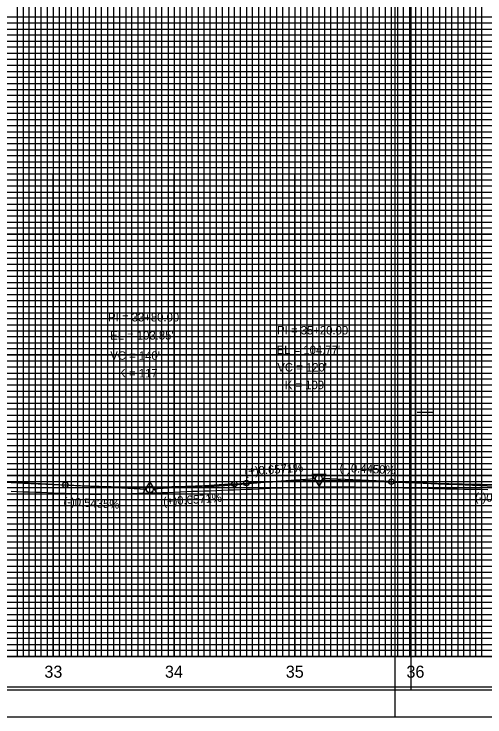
# Model space of a CAD drawing. Extents: x 2345490 to 2436403, y 465165 to 573888.
# Drawn here: x 2384034 to 2384424, y 515088 to 515670 of the extents above; entities that cross this region are included whole.
import ezdxf

# ---------------------------------------------------------------- set-up
doc = ezdxf.new("R2010")
doc.units = 0
for name, color, linetype in [('Old_Level_1', 7, 'Continuous'), ('Old_Level_18', 7, 'Continuous'), ('Old_Level_2', 7, 'Continuous'), ('Old_Level_41', 7, 'Continuous'), ('Old_Level_42', 7, 'Continuous'), ('Old_Level_43', 7, 'Continuous'), ('Old_Level_50', 7, 'Continuous'), ('Old_Level_51', 7, 'Continuous'), ('Old_Level_52', 7, 'Continuous'), ('Old_Level_57', 7, 'Continuous'), ('Old_Level_61', 7, 'Continuous'), ('Old_Level_62', 7, 'Continuous'), ('Old_Level_63', 7, 'Continuous')]:
    doc.layers.add(name, color=color, linetype=linetype)

msp = doc.modelspace()

# ---------------------------------------------------------------- linework, layer by layer
at = {"layer": 'Old_Level_1'}
for points in [[(2384031.799, 515274.675), (2384036.799, 515274.44575), (2384041.799, 515274.20725), (2384046.799, 515274.04575), (2384051.799, 515273.88425), (2384056.799, 515273.7225), (2384061.799, 515273.561), (2384066.799, 515273.325), (2384071.799, 515273.08175), (2384076.799, 515272.8975), (2384081.799, 515272.733), (2384086.799, 515272.5685), (2384091.799, 515272.404), (2384096.799, 515272.2395), (2384101.799, 515272.07525), (2384106.799, 515272.1845), (2384111.799, 515272.4225), (2384116.799, 515272.634), (2384121.799, 515272.47), (2384126.799, 515272.38825), (2384131.799, 515272.6185), (2384136.799, 515272.849), (2384141.799, 515273.0795), (2384146.799, 515273.2615), (2384151.799, 515273.335), (2384156.799, 515273.43025), (2384161.799, 515273.65775), (2384166.799, 515273.885), (2384171.799, 515274.11225), (2384176.799, 515274.34875), (2384181.799, 515274.6045), (2384186.799, 515274.76825), (2384191.799, 515274.84125), (2384196.799, 515274.91375), (2384201.799, 515275.149), (2384206.799, 515275.39775), (2384211.799, 515275.6445), (2384216.799, 515275.87125), (2384221.799, 515276.03275), (2384226.799, 515276.19275), (2384231.799, 515276.42275), (2384236.799, 515276.66), (2384241.799, 515276.8955), (2384246.799, 515277.1075), (2384251.799, 515277.259), (2384256.799, 515277.409), (2384261.799, 515277.5455), (2384266.799, 515277.6785)], [(2384266.799, 515277.6785), (2384271.799, 515277.81), (2384276.799, 515277.9495), (2384281.799, 515278.08025), (2384286.799, 515278.2065), (2384291.799, 515278.331), (2384296.799, 515278.3855), (2384301.799, 515278.29375), (2384306.799, 515278.2), (2384311.799, 515278.1535), (2384316.799, 515278.11775), (2384321.799, 515278.08), (2384326.799, 515278.02075), (2384331.799, 515277.91725), (2384336.799, 515277.81175), (2384341.799, 515277.75325), (2384346.799, 515277.7055), (2384351.799, 515277.60875), (2384356.799, 515277.495), (2384361.799, 515277.4345), (2384366.799, 515277.3775), (2384371.799, 515277.26125), (2384376.799, 515277.04725), (2384381.799, 515276.83125), (2384386.799, 515276.7395), (2384391.799, 515276.672), (2384396.799, 515276.60225), (2384401.799, 515276.47275), (2384406.799, 515276.3895), (2384411.799, 515276.3405), (2384416.799, 515276.28225), (2384421.799, 515276.2015), (2384426.799, 515276.11875)]]:
    msp.add_lwpolyline(points, dxfattribs=at)
at = {"layer": 'Old_Level_18'}
msp.add_lwpolyline([(2384616.79875, 516162.5265), (2383116.79875, 516162.5265), (2383116.79875, 515112.5265), (2384616.79875, 515112.5265)], close=True, dxfattribs=at)
at = {"layer": 'Old_Level_2'}
for p, q in [((2383991.799, 515284.4505), (2384076.799, 515279.831)), ((2384076.799, 515279.831), (2384144.05325, 515276.17575)), ((2384216.799, 515280.62675), (2384149.54325, 515276.207)), ((2384216.799, 515280.62675), (2384226.799, 515281.28375)), ((2384226.799, 515281.28375), (2384284.055, 515285.0465)), ((2384346.799, 515282.55675), (2384289.5465, 515285.1045)), ((2384346.799, 515282.55675), (2384484.05175, 515276.449))]:
    msp.add_line(p, q, dxfattribs=at)
for points in [[(2384292.72475, 515288.51125), (2384280.98225, 515288.49675), (2384286.86575, 515278.3785)], [(2384140.99325, 515272.5755), (2384152.73575, 515272.5755), (2384146.86475, 515282.70125)]]:
    msp.add_lwpolyline(points, close=True, dxfattribs=at)
for centre, radius in [((2384286.799, 515285.22675), 2.75), ((2384286.799, 515285.22675), 2.75), ((2384076.799, 515279.831), 2.25), ((2384216.799, 515280.62675), 2.25), ((2384226.799, 515281.28375), 2.25), ((2384346.799, 515282.55675), 2.25), ((2384146.799, 515276.0265), 2.75), ((2384146.799, 515276.0265), 2.75)]:
    msp.add_circle(centre, radius, dxfattribs=at)
for points in [[(2384076.799, 515279.831), (2384079.599, 515279.68225), (2384082.399, 515279.54), (2384085.199, 515279.40475), (2384087.999, 515279.276), (2384090.799, 515279.15425), (2384093.599, 515279.039), (2384096.399, 515278.9305), (2384099.199, 515278.82875), (2384101.999, 515278.73375), (2384104.799, 515278.6455), (2384107.599, 515278.56375), (2384110.399, 515278.489), (2384113.199, 515278.42075), (2384115.999, 515278.3595), (2384118.799, 515278.30475), (2384121.599, 515278.25675), (2384124.399, 515278.2155), (2384127.199, 515278.181), (2384129.999, 515278.15325), (2384132.799, 515278.13225), (2384135.599, 515278.11775), (2384138.399, 515278.11025), (2384141.199, 515278.10925), (2384143.999, 515278.11525), (2384146.799, 515278.12775), (2384149.599, 515278.147), (2384152.399, 515278.173), (2384155.199, 515278.20575), (2384157.999, 515278.24525), (2384160.799, 515278.29125), (2384163.599, 515278.34425), (2384166.399, 515278.40375), (2384169.199, 515278.47025), (2384171.999, 515278.54325), (2384174.799, 515278.623), (2384177.599, 515278.7095), (2384180.399, 515278.80275), (2384183.199, 515278.90275), (2384185.999, 515279.0095), (2384188.799, 515279.12275), (2384191.599, 515279.243), (2384194.399, 515279.36975), (2384197.199, 515279.50325), (2384199.999, 515279.64375), (2384202.799, 515279.79075), (2384205.599, 515279.9445), (2384208.399, 515280.105), (2384211.199, 515280.272), (2384213.999, 515280.446), (2384216.799, 515280.62675)], [(2384226.799, 515281.28375), (2384229.199, 515281.43875), (2384231.599, 515281.5885), (2384233.999, 515281.733), (2384236.399, 515281.87225), (2384238.799, 515282.00625), (2384241.199, 515282.13475), (2384243.599, 515282.25825), (2384245.999, 515282.37625), (2384248.399, 515282.489), (2384250.799, 515282.5965), (2384253.199, 515282.6985), (2384255.599, 515282.7955), (2384257.999, 515282.887), (2384260.399, 515282.97325), (2384262.799, 515283.05425), (2384265.199, 515283.13), (2384267.599, 515283.2005), (2384269.999, 515283.2655), (2384272.399, 515283.3255), (2384274.799, 515283.38), (2384277.199, 515283.42925), (2384279.599, 515283.47325), (2384281.999, 515283.512), (2384284.399, 515283.54525), (2384286.799, 515283.5735), (2384289.199, 515283.59625), (2384291.599, 515283.61375), (2384293.999, 515283.626), (2384296.399, 515283.633), (2384298.799, 515283.6345), (2384301.199, 515283.631), (2384303.599, 515283.622), (2384305.999, 515283.60775), (2384308.399, 515283.58825), (2384310.799, 515283.5635), (2384313.199, 515283.5335), (2384315.599, 515283.498), (2384317.999, 515283.45725), (2384320.399, 515283.41125), (2384322.799, 515283.36), (2384325.199, 515283.3035), (2384327.599, 515283.24175), (2384329.999, 515283.1745), (2384332.399, 515283.10225), (2384334.799, 515283.0245), (2384337.199, 515282.9415), (2384339.599, 515282.85325), (2384341.999, 515282.75975), (2384344.399, 515282.66075), (2384346.799, 515282.55675)], [(2384346.799, 515282.55675), (2384352.399, 515282.31325), (2384357.999, 515282.082), (2384363.599, 515281.8625), (2384369.199, 515281.65475), (2384374.799, 515281.459), (2384380.399, 515281.27525), (2384385.999, 515281.10325), (2384391.599, 515280.94325), (2384397.199, 515280.795), (2384402.799, 515280.6585), (2384408.399, 515280.53425), (2384413.999, 515280.4215), (2384419.599, 515280.32075), (2384425.199, 515280.232), (2384430.799, 515280.155), (2384436.399, 515280.09), (2384441.999, 515280.03675), (2384447.599, 515279.9955), (2384453.199, 515279.966), (2384458.799, 515279.9485), (2384464.399, 515279.943), (2384469.999, 515279.949), (2384475.599, 515279.96725), (2384481.199, 515279.99725), (2384486.799, 515280.039), (2384492.399, 515280.09275), (2384497.999, 515280.15825), (2384503.599, 515280.23575), (2384509.199, 515280.32525), (2384514.799, 515280.4265), (2384520.399, 515280.5395), (2384525.999, 515280.6645), (2384531.599, 515280.8015), (2384537.199, 515280.95025), (2384542.799, 515281.111), (2384548.399, 515281.2835), (2384553.999, 515281.46775), (2384559.599, 515281.66425), (2384565.199, 515281.87225), (2384570.799, 515282.09225), (2384576.399, 515282.32425), (2384581.999, 515282.568), (2384587.599, 515282.82375), (2384593.199, 515283.09125), (2384598.799, 515283.37075), (2384604.399, 515283.66225), (2384609.999, 515283.96525), (2384615.599, 515284.2805), (2384621.199, 515284.6075), (2384626.799, 515284.94625)]]:
    msp.add_spline(points, degree=3, dxfattribs=at)
at = {"layer": 'Old_Level_41'}
for p, q in [((2384368.29875, 515340.0265), (2384380.79875, 515340.0265)), ((2384616.79875, 515137.5265), (2383116.79875, 515137.5265))]:
    msp.add_line(p, q, dxfattribs=at)
for points in [[(2384041.79875, 516162.5265), (2384041.79875, 515137.5265), (2384091.79875, 515137.5265), (2384091.79875, 516162.5265)], [(2384066.79875, 516162.5265), (2384066.79875, 515137.5265), (2384116.79875, 515137.5265), (2384116.79875, 516162.5265)], [(2384141.79875, 516162.5265), (2384141.79875, 515137.5265), (2384191.79875, 515137.5265), (2384191.79875, 516162.5265)], [(2384166.79875, 516162.5265), (2384166.79875, 515137.5265), (2384216.79875, 515137.5265), (2384216.79875, 516162.5265)], [(2384241.79875, 516162.5265), (2384241.79875, 515137.5265), (2384291.79875, 515137.5265), (2384291.79875, 516162.5265)], [(2384266.79875, 516162.5265), (2384266.79875, 515137.5265), (2384316.79875, 515137.5265), (2384316.79875, 516162.5265)], [(2384341.79875, 516162.5265), (2384341.79875, 515137.5265), (2384391.79875, 515137.5265), (2384391.79875, 516162.5265)], [(2384366.79875, 516162.5265), (2384366.79875, 515137.5265), (2384416.79875, 515137.5265), (2384416.79875, 516162.5265)], [(2384616.79875, 515662.5265), (2383116.79875, 515662.5265), (2383116.79875, 515612.5265), (2384616.79875, 515612.5265)], [(2384616.79875, 515562.5265), (2383116.79875, 515562.5265), (2383116.79875, 515512.5265), (2384616.79875, 515512.5265)], [(2384616.79875, 515487.5265), (2383116.79875, 515487.5265), (2383116.79875, 515537.5265), (2384616.79875, 515537.5265)], [(2384616.79875, 515462.5265), (2383116.79875, 515462.5265), (2383116.79875, 515412.5265), (2384616.79875, 515412.5265)], [(2384616.79875, 515387.5265), (2383116.79875, 515387.5265), (2383116.79875, 515437.5265), (2384616.79875, 515437.5265)], [(2384616.79875, 515362.5265), (2383116.79875, 515362.5265), (2383116.79875, 515312.5265), (2384616.79875, 515312.5265)], [(2384616.79875, 515262.5265), (2383116.79875, 515262.5265), (2383116.79875, 515212.5265), (2384616.79875, 515212.5265)], [(2384616.79875, 515187.5265), (2383116.79875, 515187.5265), (2383116.79875, 515237.5265), (2384616.79875, 515237.5265)], [(2384616.79875, 515162.5265), (2383116.79875, 515162.5265)]]:
    msp.add_lwpolyline(points, dxfattribs=at)
at = {"layer": 'Old_Level_42'}
for points in [[(2384616.79875, 515587.5265), (2383116.79875, 515587.5265), (2383116.79875, 515637.5265), (2384616.79875, 515637.5265)], [(2384616.79875, 515287.5265), (2383116.79875, 515287.5265), (2383116.79875, 515337.5265), (2384616.79875, 515337.5265)]]:
    msp.add_lwpolyline(points, dxfattribs=at)
at = {"layer": 'Old_Level_43'}
for points in [[(2384036.79875, 516162.5265), (2384036.79875, 515137.5265), (2384046.79875, 515137.5265), (2384046.79875, 516162.5265)], [(2384051.79875, 516162.5265), (2384051.79875, 515137.5265), (2384056.79875, 515137.5265), (2384056.79875, 516162.5265)], [(2384061.79875, 516162.5265), (2384061.79875, 515137.5265), (2384071.79875, 515137.5265), (2384071.79875, 516162.5265)], [(2384076.79875, 516162.5265), (2384076.79875, 515137.5265), (2384081.79875, 515137.5265), (2384081.79875, 516162.5265)], [(2384086.79875, 516162.5265), (2384086.79875, 515137.5265), (2384096.79875, 515137.5265), (2384096.79875, 516162.5265)], [(2384101.79875, 516162.5265), (2384101.79875, 515137.5265), (2384106.79875, 515137.5265), (2384106.79875, 516162.5265)], [(2384111.79875, 516162.5265), (2384111.79875, 515137.5265), (2384121.79875, 515137.5265), (2384121.79875, 516162.5265)], [(2384126.79875, 516162.5265), (2384126.79875, 515137.5265), (2384131.79875, 515137.5265), (2384131.79875, 516162.5265)], [(2384136.79875, 516162.5265), (2384136.79875, 515137.5265), (2384146.79875, 515137.5265), (2384146.79875, 516162.5265)], [(2384151.79875, 516162.5265), (2384151.79875, 515137.5265), (2384156.79875, 515137.5265), (2384156.79875, 516162.5265)], [(2384161.79875, 516162.5265), (2384161.79875, 515137.5265), (2384171.79875, 515137.5265), (2384171.79875, 516162.5265)], [(2384176.79875, 516162.5265), (2384176.79875, 515137.5265), (2384181.79875, 515137.5265), (2384181.79875, 516162.5265)], [(2384186.79875, 516162.5265), (2384186.79875, 515137.5265)], [(2384186.79875, 515137.5265), (2384196.79875, 515137.5265), (2384196.79875, 516162.5265)], [(2384201.79875, 516162.5265), (2384201.79875, 515137.5265), (2384206.79875, 515137.5265), (2384206.79875, 516162.5265)], [(2384211.79875, 516162.5265), (2384211.79875, 515137.5265), (2384221.79875, 515137.5265), (2384221.79875, 516162.5265)], [(2384226.79875, 516162.5265), (2384226.79875, 515137.5265), (2384231.79875, 515137.5265), (2384231.79875, 516162.5265)], [(2384236.79875, 516162.5265), (2384236.79875, 515137.5265), (2384246.79875, 515137.5265), (2384246.79875, 516162.5265)], [(2384251.79875, 516162.5265), (2384251.79875, 515137.5265), (2384256.79875, 515137.5265), (2384256.79875, 516162.5265)], [(2384261.79875, 516162.5265), (2384261.79875, 515137.5265), (2384271.79875, 515137.5265), (2384271.79875, 516162.5265)], [(2384276.79875, 516162.5265), (2384276.79875, 515137.5265), (2384281.79875, 515137.5265), (2384281.79875, 516162.5265)], [(2384286.79875, 516162.5265), (2384286.79875, 515137.5265), (2384296.79875, 515137.5265), (2384296.79875, 516162.5265)], [(2384301.79875, 516162.5265), (2384301.79875, 515137.5265), (2384306.79875, 515137.5265), (2384306.79875, 516162.5265)], [(2384311.79875, 516162.5265), (2384311.79875, 515137.5265), (2384321.79875, 515137.5265), (2384321.79875, 516162.5265)], [(2384326.79875, 516162.5265), (2384326.79875, 515137.5265), (2384331.79875, 515137.5265), (2384331.79875, 516162.5265)], [(2384336.79875, 516162.5265), (2384336.79875, 515137.5265), (2384346.79875, 515137.5265), (2384346.79875, 516162.5265)], [(2384351.79875, 516162.5265), (2384351.79875, 515137.5265), (2384356.79875, 515137.5265), (2384356.79875, 516162.5265)], [(2384361.79875, 516162.5265), (2384361.79875, 515137.5265), (2384371.79875, 515137.5265), (2384371.79875, 516162.5265)], [(2384376.79875, 516162.5265), (2384376.79875, 515137.5265), (2384381.79875, 515137.5265), (2384381.79875, 516162.5265)], [(2384386.79875, 516162.5265), (2384386.79875, 515137.5265), (2384396.79875, 515137.5265), (2384396.79875, 516162.5265)], [(2384401.79875, 516162.5265), (2384401.79875, 515137.5265), (2384406.79875, 515137.5265), (2384406.79875, 516162.5265)], [(2384411.79875, 516162.5265), (2384411.79875, 515137.5265), (2384421.79875, 515137.5265), (2384421.79875, 516024.9765)], [(2384566.79875, 515667.5265), (2383166.79875, 515667.5265), (2383166.79875, 515657.5265), (2384566.79875, 515657.5265)], [(2384566.79875, 515652.5265), (2383166.79875, 515652.5265), (2383166.79875, 515647.5265), (2384566.79875, 515647.5265)], [(2384566.79875, 515642.5265), (2383166.79875, 515642.5265)], [(2383166.79875, 515632.5265), (2384566.79875, 515632.5265)], [(2384566.79875, 515627.5265), (2383166.79875, 515627.5265), (2383166.79875, 515622.5265), (2384566.79875, 515622.5265)], [(2384566.79875, 515617.5265), (2383166.79875, 515617.5265), (2383166.79875, 515607.5265), (2384566.79875, 515607.5265)], [(2384566.79875, 515602.5265), (2383166.79875, 515602.5265), (2383166.79875, 515597.5265), (2384566.79875, 515597.5265)], [(2384566.79875, 515592.5265), (2383166.79875, 515592.5265), (2383166.79875, 515582.5265), (2384566.79875, 515582.5265)], [(2384566.79875, 515577.5265), (2383166.79875, 515577.5265), (2383166.79875, 515572.5265), (2384566.79875, 515572.5265)], [(2384566.79875, 515567.5265), (2383166.79875, 515567.5265), (2383166.79875, 515557.5265), (2384566.79875, 515557.5265)], [(2384566.79875, 515552.5265), (2383166.79875, 515552.5265), (2383166.79875, 515547.5265), (2384566.79875, 515547.5265)], [(2384566.79875, 515542.5265), (2383166.79875, 515542.5265), (2383166.79875, 515532.5265), (2384566.79875, 515532.5265)], [(2384566.79875, 515527.5265), (2383166.79875, 515527.5265), (2383166.79875, 515522.5265), (2384566.79875, 515522.5265)], [(2384566.79875, 515517.5265), (2383166.79875, 515517.5265), (2383166.79875, 515507.5265), (2384566.79875, 515507.5265)], [(2384566.79875, 515502.5265), (2383166.79875, 515502.5265), (2383166.79875, 515497.5265), (2384566.79875, 515497.5265)], [(2384566.79875, 515492.5265), (2383166.79875, 515492.5265), (2383166.79875, 515482.5265), (2384566.79875, 515482.5265)], [(2384566.79875, 515477.5265), (2383166.79875, 515477.5265), (2383166.79875, 515472.5265), (2384566.79875, 515472.5265)], [(2384566.79875, 515467.5265), (2383166.79875, 515467.5265), (2383166.79875, 515457.5265), (2384566.79875, 515457.5265)], [(2384566.79875, 515452.5265), (2383166.79875, 515452.5265), (2383166.79875, 515447.5265), (2384566.79875, 515447.5265)], [(2384566.79875, 515442.5265), (2383166.79875, 515442.5265), (2383166.79875, 515432.5265), (2384566.79875, 515432.5265)], [(2384566.79875, 515427.5265), (2383166.79875, 515427.5265), (2383166.79875, 515422.5265), (2384566.79875, 515422.5265)], [(2384566.79875, 515417.5265), (2383166.79875, 515417.5265), (2383166.79875, 515407.5265), (2384566.79875, 515407.5265)], [(2384566.79875, 515402.5265), (2383166.79875, 515402.5265), (2383166.79875, 515397.5265), (2384566.79875, 515397.5265)], [(2384566.79875, 515392.5265), (2383166.79875, 515392.5265), (2383166.79875, 515382.5265), (2384566.79875, 515382.5265)], [(2384566.79875, 515377.5265), (2383166.79875, 515377.5265), (2383166.79875, 515372.5265), (2384566.79875, 515372.5265)], [(2384566.79875, 515367.5265), (2383166.79875, 515367.5265), (2383166.79875, 515357.5265), (2384566.79875, 515357.5265)], [(2384566.79875, 515352.5265), (2383166.79875, 515352.5265), (2383166.79875, 515347.5265), (2384566.79875, 515347.5265)], [(2384566.79875, 515342.5265), (2383166.79875, 515342.5265)], [(2383166.79875, 515332.5265), (2384566.79875, 515332.5265)], [(2384566.79875, 515327.5265), (2383166.79875, 515327.5265), (2383166.79875, 515322.5265), (2384566.79875, 515322.5265)], [(2384566.79875, 515317.5265), (2383166.79875, 515317.5265)], [(2383166.79875, 515307.5265), (2384566.79875, 515307.5265)], [(2384566.79875, 515302.5265), (2383166.79875, 515302.5265), (2383166.79875, 515297.5265), (2384566.79875, 515297.5265)], [(2384566.79875, 515292.5265), (2383166.79875, 515292.5265), (2383166.79875, 515282.5265), (2384566.79875, 515282.5265)], [(2384566.79875, 515277.5265), (2383166.79875, 515277.5265), (2383166.79875, 515272.5265), (2384566.79875, 515272.5265)], [(2384566.79875, 515267.5265), (2383166.79875, 515267.5265), (2383166.79875, 515257.5265), (2384566.79875, 515257.5265)], [(2384566.79875, 515252.5265), (2383166.79875, 515252.5265), (2383166.79875, 515247.5265), (2384566.79875, 515247.5265)], [(2384566.79875, 515242.5265), (2383166.79875, 515242.5265), (2383166.79875, 515232.5265), (2384566.79875, 515232.5265)], [(2384566.79875, 515227.5265), (2383166.79875, 515227.5265), (2383166.79875, 515222.5265), (2384566.79875, 515222.5265)], [(2384566.79875, 515217.5265), (2383166.79875, 515217.5265), (2383166.79875, 515207.5265), (2384566.79875, 515207.5265)], [(2384566.79875, 515202.5265), (2383166.79875, 515202.5265), (2383166.79875, 515197.5265), (2384566.79875, 515197.5265)], [(2384566.79875, 515192.5265), (2383166.79875, 515192.5265), (2383166.79875, 515182.5265), (2384566.79875, 515182.5265)], [(2384566.79875, 515177.5265), (2383166.79875, 515177.5265), (2383166.79875, 515172.5265), (2384566.79875, 515172.5265)], [(2384566.79875, 515167.5265), (2383166.79875, 515167.5265), (2383166.79875, 515157.5265), (2384566.79875, 515157.5265)], [(2384566.79875, 515152.5265), (2383166.79875, 515152.5265), (2383166.79875, 515147.5265), (2384566.79875, 515147.5265)], [(2384566.79875, 515142.5265), (2383166.79875, 515142.5265)]]:
    msp.add_lwpolyline(points, dxfattribs=at)
at = {"layer": 'Old_Level_50'}
msp.add_line((2384349.79875, 515087.5265), (2384349.79875, 515087.5265), dxfattribs=at)
for points in [[(2384629.29875, 516165.0765), (2382962.79875, 516165.0765), (2382962.79875, 515109.9765), (2384629.29875, 515109.9765)], [(2386029.29875, 516165.0765), (2384362.79875, 516165.0765), (2384362.79875, 515109.9765), (2386029.29875, 515109.9765)]]:
    msp.add_lwpolyline(points, close=True, dxfattribs=at)
at = {"layer": 'Old_Level_51'}
for points in [[(2384633.79875, 516187.5265), (2382949.79875, 516187.5265), (2382949.79875, 515087.5265), (2384633.79875, 515087.5265)], [(2386033.79875, 516187.5265), (2384349.79875, 516187.5265), (2384349.79875, 515087.5265), (2386033.79875, 515087.5265)]]:
    msp.add_lwpolyline(points, close=True, dxfattribs=at)
at = {"layer": 'Old_Level_52'}
msp.add_line((2384362.79875, 515109.9765), (2384362.79875, 515109.9765), dxfattribs=at)
at = {"layer": 'Old_Level_57'}
for p, q in [((2381716.79925, 515537.52675), (2386366.79875, 515537.52675)), ((2384066.79875, 515137.52675), (2384066.79875, 515537.52675)), ((2384066.79875, 515137.62675), (2384066.79875, 515537.52675)), ((2384166.79875, 515137.52675), (2384166.79875, 515537.52675)), ((2384166.79875, 515137.62675), (2384166.79875, 515537.52675)), ((2384266.79875, 515137.52675), (2384266.79875, 515537.52675)), ((2384266.79875, 515137.62675), (2384266.79875, 515537.52675)), ((2384366.79875, 515137.52675), (2384366.79875, 515537.52675)), ((2384366.79875, 515137.62675), (2384366.79875, 515537.52675)), ((2381716.79925, 515487.52675), (2386366.79875, 515487.52675)), ((2381716.79925, 515437.52675), (2386366.79875, 515437.52675)), ((2381716.79925, 515387.52675), (2386366.79875, 515387.52675)), ((2381716.79925, 515337.52675), (2386366.79875, 515337.52675)), ((2381716.79925, 515287.52675), (2386366.79875, 515287.52675)), ((2381716.79925, 515237.52675), (2386366.79875, 515237.52675)), ((2381716.799, 515187.52675), (2386366.79875, 515187.52675)), ((2381716.79925, 515137.52675), (2386366.79875, 515137.52675))]:
    msp.add_line(p, q, dxfattribs=at)
at = {"layer": 'Old_Level_61'}
msp.add_lwpolyline([(2384016.799, 515282.61625), (2384041.799, 515281.37825), (2384066.799, 515280.16925), (2384091.799, 515279.062), (2384116.799, 515278.24625), (2384141.799, 515277.7265), (2384166.799, 515277.90875), (2384191.799, 515278.191), (2384216.799, 515279.86425), (2384241.799, 515282.13275), (2384266.799, 515283.16125), (2384291.799, 515283.267), (2384316.799, 515282.8155), (2384341.799, 515282.29975), (2384366.799, 515281.624), (2384391.799, 515280.5605), (2384416.799, 515280.1045), (2384441.799, 515279.8205)], dxfattribs=at)
at = {"layer": 'Old_Level_63'}
msp.add_line((2381766.79875, 515137.5265), (2386228.05125, 515137.5265), dxfattribs=at)

# ---------------------------------------------------------------- texts
at = {"layer": 'Old_Level_2'}
for s, height, p in [('PI = 33+80.00', 7.0000005, (2384112.21425, 515415.28925)), ('PI = 35+20.00', 7.0000005, (2384252.21425, 515404.4895)), ("EL = 103.85'", 7.0000005, (2384113.87475, 515400.2725)), ("VC = 140'", 7.000001, (2384114.00325, 515383.5355)), ("EL = 104.77'", 7.0000005, (2384251.799, 515388.22675)), ("VC = 120'", 7.000001, (2384252.34225, 515373.79275)), ('K = 117', 7.000001, (2384120.64525, 515368.8815)), ('K = 109', 7.000001, (2384258.56925, 515359.139))]:
    msp.add_text(s, height=height, dxfattribs=at).set_placement(p)
for s, rotation, p in [('(+)0.6571%', 3.75974444, (2384225.342, 515287.58025)), ('(-)0.4450%', 357.45201944, (2384303.81325, 515290.70125)), ('(-)0.4450%', 357.45201944, (2384415.96725, 515266.4195)), ('(-)0.5435%', 356.88915833, (2384075.05525, 515262.58775)), ('(+)0.6571%', 3.75974444, (2384157.9745, 515262.6035))]:
    msp.add_text(s, height=7.000001, rotation=rotation, dxfattribs=at).set_placement(p)
at = {"layer": 'Old_Level_62'}
for s, p in [('33', (2384059.408, 515120.0265)), ('34', (2384159.2505, 515120.0265)), ('35', (2384259.343, 515120.0265)), ('36', (2384359.284, 515120.0265))]:
    msp.add_text(s, height=10.000001, dxfattribs=at).set_placement(p)

doc.saveas('drawing.dxf')
